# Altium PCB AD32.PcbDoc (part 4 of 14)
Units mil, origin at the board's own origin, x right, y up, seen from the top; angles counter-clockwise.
Board outline 7007.87 x 4368.85 mil, 12 copper layers (Top Layer, Int1 (GND), Int2 (AVDD), Int3 (DVDD), Int4 (GND), Int5 (ST), Int6 (SB), Int8 (AGND), Int7 (AVCC), Int9 (VCCA), Int10 (GND), Bottom Layer), stack 60.136 mil thick; 1350 components, 880 nets, 4712 pads, 2835 vias.
Unrouted connection lines stored in the file: 19.
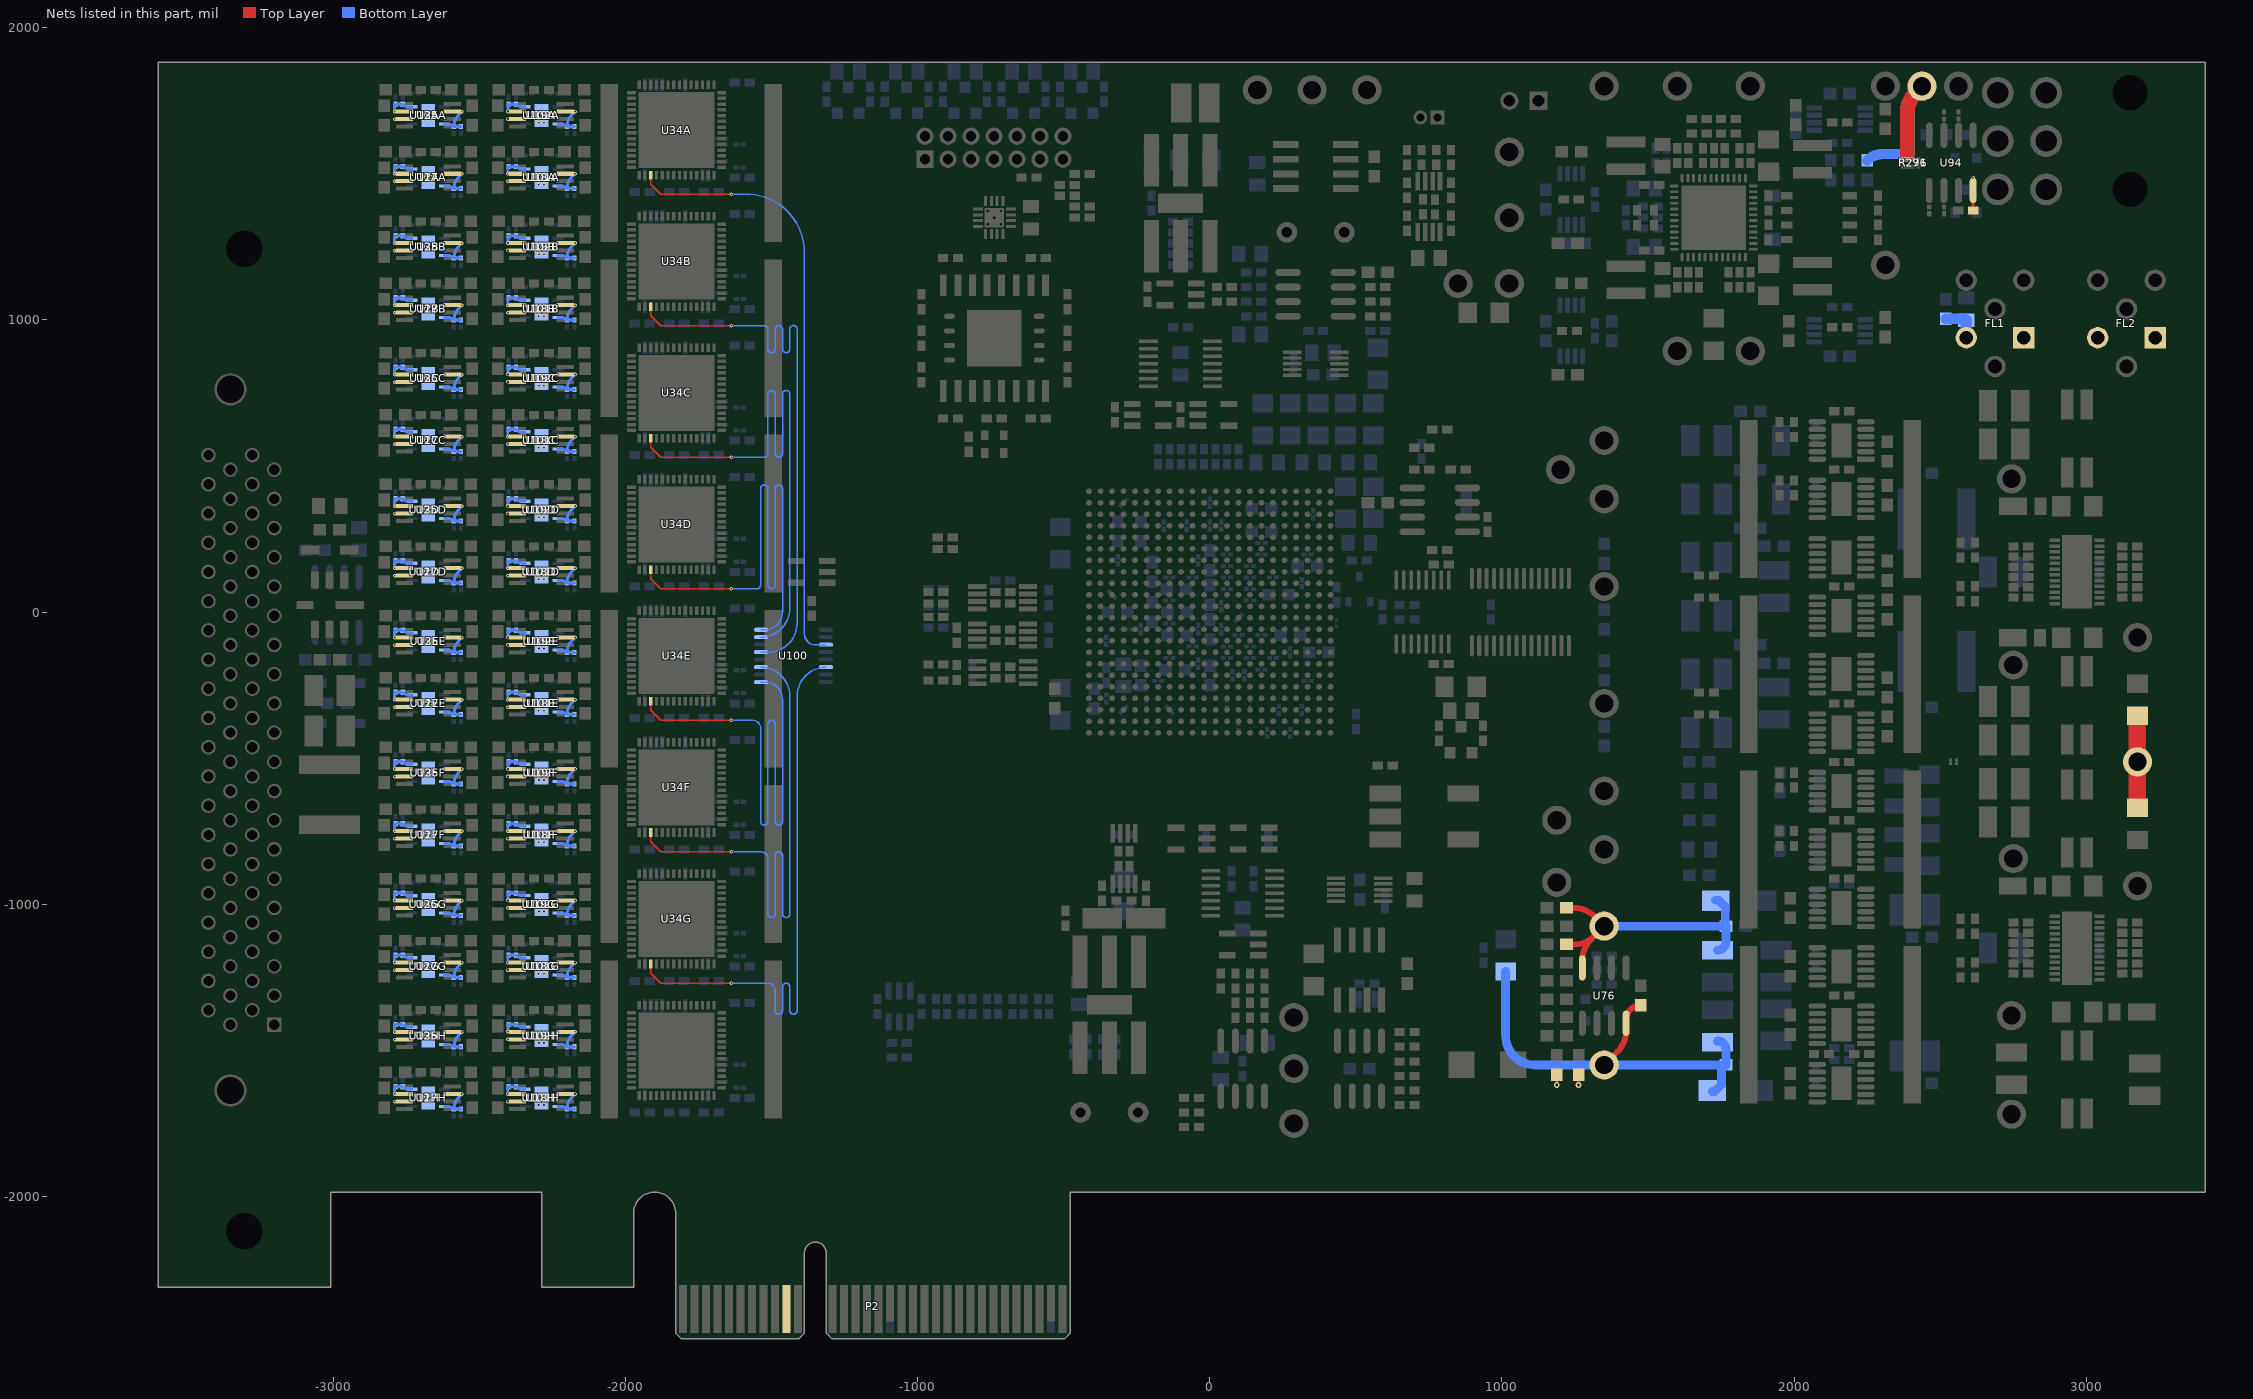
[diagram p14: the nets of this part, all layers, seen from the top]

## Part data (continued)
L3: library part CMP-11268-000187-1, "Fixed Inductors 3.3Uh Shld 5.2A 38.3mOhms AECQ2", Part Number=XFL4020-332MEC, Supplier Part Number 1=2457-XFL4020-332MEC-ND
L4: library part CMP-11268-000008-1, "INDUCTOR, 4.7uH", Part Number=XFL4020-472MEB
L5: library part MSD7342, "Shielded Coupled Inductors, MSD7342 series 4.7uH", Part Number=MSD7342-472MLC, Supplier Part Number 1=994-MSD7342-472MLC
L6 L7 L8: library part MSD7342, "Shielded Coupled Inductors, MSD7342 series 8.2uH", Part Number=MSD7342-822MLC, Supplier Part Number 1=994-MSD7342-822MLC
L9: library part ChipInductor, "Inductor", Part Number=1008CS-330XJRC, Supplier Part Number 1=2457-1008CS-330XJRC-ND
L10: library part ChipInductor, "Inductor", Part Number=1008CS-101XJRC, Supplier Part Number 1=2457-1008CS-101XJRC-ND
LOGO1: library part LIGO_logo, "NL"
MP1 MP2 MP3 MP4 MP5 MP6 MP7 MP8 MP9 MP10: library part CMP-33535-000006-1, "HEATSINK FOR TO-263", Supplier Part Number 1=DA-T263-201ECT-ND
P1: library part "PE50E-080 Connector", "3M Pak 50 plug connector", Part Number=P50E-080P1-RR1-EA, Supplier Part Number 1=3M161985-ND
P2: library part CMP-0001-00031-2, "NL"
P3: library part Xilinx_JTAG_Header, "Xilinx JTAG header, 7-Pin, Dual row", Part Number=WM18863-ND
P4: library part WM4200, "Header, 2-Pin", Supplier Part Number 1=900-0022232021-ND
Q1 Q6 Q7 Q8 Q9 Q10: "FDV301N, Digital FET, N-channel, SOT23", Part Number=FDV301NCT-ND
Q2: library part CMP-2000-07602-1, "Mosfet Array 30V 17A 2.8W Surface Mount 8-DFN (5x6)", Supplier Part Number 1=785-1499-1-ND
Q3 Q4 Q5: library part CMP-1048-00670-1, "General Purpose Transistor, PNP Silicon, 3-Pin SOT-23, Pb-Free, Tape and Reel", Supplier Part Number 1=MMBT3906LT1GOSCT-ND
R1 R197 R209 R240 R267 R537A R537B R537C R537D R537E R537F R537G R537H R538A R538B R538C R538D R538E R538F R538G R538H R585A R585B R585C R585D R585E R585F R585G R585H R593A R593B R593C R593D R593E R593F R593G R593H R601A R601B R601C R601D R601E R601F R601G R601H R609A R609B R609C R609D R609E R609F R609G R609H R649A R649B R649C R649D R649E R649F R649G R649H R657A R657B R657C R657D R657E R657F R657G R657H: library part ChipRes1, "R0603 10k", Part Number=ERA-3ARB103V, Supplier Part Number 1=P10KBDCT-ND
R2 R8 R20A R20B R20C R20D R20E R20F R20G R20H R28A R28B R28C R28D R28E R28F R28G R28H R36A R36B R36C R36D R36E R36F R36G R36H R44A R44B R44C R44D R44E R44F R44G R44H R84A R84B R84C R84D R84E R84F R84G R84H R92A R92B R92C R92D R92E R92F R92G R92H R100A R100B R100C R100D R100E R100F R100G R100H R108A R108B R108C R108D R108E R108F R108G R108H R665 R666: library part ChipRes1, "R0603 100", Part Number=ERA-3AEB101V, Supplier Part Number 1=P100DBCT-ND
R3: library part ChipRes1, "R0603 680", Part Number=RG1608P-681-B-T5, Supplier Part Number 1=RG16P680BCT-ND
R4A R4B R4C R4D R4E R4F R4G R4H R12A R12B R12C R12D R12E R12F R12G R12H R52A R52B R52C R52D R52E R52F R52G R52H R60A R60B R60C R60D R60E R60F R60G R60H R68A R68B R68C R68D R68E R68F R68G R68H R76A R76B R76C R76D R76E R76F R76G R76H R116A R116B R116C R116D R116E R116F R116G R116H R124A R124B R124C R124D R124E R124F R124G R124H: library part ChipRes1, "R0603 2.05k", Part Number=RN73C1J2K05BTD, Supplier Part Number 1=A123338CT-ND
R5 R7 R184 R193 R353 R354 R390 R391: library part ChipRes1, "R0402 49.9", Part Number=ERA-2AEB49R9X, Supplier Part Number 1=P49.9DCCT-ND
R6 R135 R136 R137 R138 R139 R142 R143 R148 R149 R150 R151 R152 R153 R162 R163 R164 R166 R167 R188 R190 R259 R328 R331 R335 R341 R368 R370 R386 R395 R397: library part ChipRes1, "R0402 NL"
R132 R141 R144 R147 R154 R159 R205 R206 R246 R256 R357 R371 R372 R374 R375: library part ChipRes1, "R0402 100", Part Number=TNPW0402100RBEED, Supplier Part Number 1=TNP100DACT-ND
R133 R134 R146 R158 R160: library part ChipRes1, "R0402 1.8k", Part Number=RR05P1.8KDCT-ND
R140 R169 R195 R373 R380 R388 R393 R398 R400: library part ChipRes1, "R0402 1.0k", Part Number=RT0402BRD071KL, Supplier Part Number 1=YAG1386CT-ND
R145 R155 R191 R293 R294 R365 R366 R367 R369 R378 R379 R381 R389 R394 R399: library part ChipRes1, "R0402 4.7k", Part Number=ERA-2AED472X, Supplier Part Number 1=P4.7KDECT-ND
R156 R157 R382: library part ChipRes1, "R0201 100", Part Number=RR0306P-101-D, Supplier Part Number 1=RR03P100DCT-ND
R161 R165: library part ChipRes1, "R0603 NL"
R168 R170 R171 R172 R173 R174 R176 R178 R179 R181 R182 R219 R225 R228 R315 R336 R339 R342 R344 R355 R361 R362: library part ChipRes1, "R0402 10k", Part Number=ERA-2AEB103X, Supplier Part Number 1=P10KDCCT-ND
R175 R180 R216 R360 R363: library part ChipRes1, "R0402 15k", Part Number=ERA-2AEB153X, Supplier Part Number 1=P15KDCCT-ND
R177 R203 R212 R304 R325 R352: library part ChipRes1, "R0603 1.0k", Part Number=RR0816P-102-D, Supplier Part Number 1=RR08P1.0KDCT-ND
R183 R220 R222 R316 R317 R337 R345 R392: library part ChipRes1, "R0402 22k", Part Number=ERA-2AED223X, Supplier Part Number 1=P22KDECT-ND
R185 R305 R307 R387: library part ChipRes1, "R0402 2.32k", Part Number=RT0402BRD072K32L, Supplier Part Number 1=YAG4228CT-ND
R186 R192: library part ChipRes1, "R0402 200k", Part Number=MCS04020D2003BE000, Supplier Part Number 1=749-MCS04020D2003BE000CT-ND
R187 R189 R277 R278 R281 R284 R376 R377: library part ChipRes1, "R0402 2k", Part Number=ERA-2AEB202X, Supplier Part Number 1=P2.0KDCCT-ND
R194 R384 R385: library part ChipRes1, "R0402 1.6k", Part Number=ERA-2AEB162X, Supplier Part Number 1=P1.6KDCCT-ND
R196 R199 R200 R201 R208 R233 R268 R308 R320 R321 R322 R323 R332 R333 R334: library part ChipRes1, "R0603 220", Part Number=ERA3AEB221V, Supplier Part Number 1=P220DBCT-ND
R198: library part ChipRes1, "R0603 1.37k", Part Number=ERA-3AEB1371V, Supplier Part Number 1=P1.37KDBCT-ND
R202 R207 R303: library part ChipRes1, "R0603 59k", Part Number=ERA-3AEB5902V, Supplier Part Number 1=P59KDBCT-ND
R204: library part ChipRes1, "R0603 3.7k", Part Number=RN73R1JTTD3701B25, Supplier Part Number 1=2019-RN73R1JTTD3701B25CT-ND
R210 R211 R236 R237 R238 R239 R243 R260 R261 R262 R263 R264 R265 R266 R298 R301 R302 R326 R327 R348 R349 R350 R351: library part ChipRes1, "R0603 10m", Part Number=CFN0603AFZ-R010ELF, Supplier Part Number 1=118-CFN0603AFZ-R010ELFCT-ND
R213 R214 R245 R255: library part ChipRes1, "R0603 5.23k", Part Number=ERA-3AEB5231V, Supplier Part Number 1=P5.23KDBCT-ND
R215 R358 R364: library part ChipRes1, "R0402 4.99k", Part Number=RR0510P-4991-D, Supplier Part Number 1=RR05P4.99KDCT-ND
R217: library part ChipRes1, "R0402 9.31k", Part Number=RT0402BRD079K31L, Supplier Part Number 1=YAG4325CT-ND
R218: library part ChipRes1, "R0402 21.5k", Part Number=RR0510P-2152-D, Supplier Part Number 1=408-RR0510P-2152-DCT-ND
R221 R223 R235 R306 R311: library part ChipRes1, "R0402 100k", Part Number=ERA-2AEB104X, Supplier Part Number 1=P100KDCCT-ND
R224: library part ChipRes1, "R0402 31.6k", Part Number=RT0402DRE0731K6L, Supplier Part Number 1=311-2272-1-ND
R226: library part ChipRes1, "R0402 12.7k", Part Number=RT0402DRE0712K7L, Supplier Part Number 1=311-2223-1-ND
R227: library part ChipRes1, "R0402 37.4k", Part Number=CR0402-FX-3742GLF, Supplier Part Number 1=YAG4250CT-ND
R229: library part ChipRes1, "R0402 7.15k", Part Number=RT0402BRD077K15L, Supplier Part Number 1=YAG1478CT-ND
R230: library part ChipRes1, "R0402 56.2k", Part Number=RT0402DRE0756K2L, Supplier Part Number 1=311-2303-1-ND
R231 R232: library part ChipRes1, "R0603 9.09k", Part Number=ERA-3AEB9091V, Supplier Part Number 1=P9.09KDBCT-ND
R234: library part ChipRes1, "R0402 130k", Part Number=RP73PF1E130KBTD, Supplier Part Number 1=A127522CT-ND
R241 R242 R312 R313: library part ChipRes1, "R0402 49.9k", Part Number=RR0510P-4992-D, Supplier Part Number 1=RR05P49.9KDCT-ND
R244: library part ChipRes1, "R0402 267k", Part Number=ERJ-2RKF2673X, Supplier Part Number 1=P267KLCT-ND
R247 R248 R252 R257: library part ChipRes1, "R0402 150", Part Number=ERA-2AEB151X, Supplier Part Number 1=P150DCCT-ND
R249 R250 R253 R254: library part ChipRes1, "R0402 300", Part Number=RR05P300DCT-ND
R251: library part ChipRes1, "R0402 249k", Part Number=RP73PF1E249KBTD, Supplier Part Number 1=A127549CT-ND
R258: library part ChipRes1, "R0402 47k", Part Number=RG1005P-473-B-T5, Supplier Part Number 1=RG10P47KBCT-ND
R269 R270 R272 R297: library part ChipRes1, "R0201 1k", Part Number=ERA-1AEB102C, Supplier Part Number 1=P1.0KBXCT-ND
R271 R296: library part RW1S0CK, "Four-Terminal Current Sense Resistor", Supplier Part Number 1=273-FC4L16R010FERCT-ND, Tolerance=0.5%
R273 R274: library part ChipRes1, "R0402 162k", Supplier Part Number 1=A127531CT-ND
R275: library part ChipRes1, "R0402 15.6k", Supplier Part Number 1=2019-RN73R1ETTP1562B25DKR-ND
R276: library part ChipRes1, "R0402 57.6k", Part Number=RT0402DRD0734K8L, Supplier Part Number 1=2019-RN73H1ETTP5762B25CT-ND
R279: library part ChipRes1, "R0402 14.7k", Part Number=RT0402BRD0714K7L, Supplier Part Number 1=YAG4174CT-ND
R280 R282 R283 R324 R330: library part ChipRes1, "R0402 0", Part Number=AC0402FR-070RL, Supplier Part Number 1=13-AC0402FR-070RLCT-ND
R285 R286 R288 R291: library part ChipRes1, "R0402 76.8k", Part Number=RT0402DRE0776K8L, Supplier Part Number 1=311-2319-1-ND
R287 R289 R290 R292: library part ChipRes1, "R0402 715k", Part Number=RC0402FR-07715KL, Supplier Part Number 1=YAG3221CT-ND
R295: library part ChipRes1, "R0603 15k", Part Number=ERA-3ARB153V, Supplier Part Number 1=P15KBDCT-ND
R299 R300: library part ChipRes1, "R0603 0", Part Number=RC0603JR-070RL, Supplier Part Number 1=311-0.0GRCT-ND
R309 R310: library part ChipRes1, "R0402 56.2k"
R314: library part ChipRes1, "R0402 12.1k", Part Number=ERA-2AEB1212X, Supplier Part Number 1=P12.1KDCCT-ND
R318 R319: library part ChipRes1, "R0402 330k", Part Number=MCS0402MD3303BE000, Supplier Part Number 1=541-MCS0402MD3303BE000CT-ND
R329: library part ChipRes1, "R0402 40.2k", Part Number=ERA-2ARC4022X, Supplier Part Number 1=P18270CT-ND
R338: library part ChipRes1, "R0402 402k", Part Number=RMCF0402FT402KCT-ND
R340: library part ChipRes1, "R0402 301k", Part Number=RMCF0402FT301KCT-ND
R343: library part ChipRes1, "R0402 1.91k", Part Number=RT0402BRD071K91L, Supplier Part Number 1=YAG4201CT-ND
R346: library part ChipRes1, "R0402 3k", Supplier Part Number 1=P3.0KDCCT-ND
R347: library part ChipRes1, "R0402 30k", Part Number=ERA-2AEB303X, Supplier Part Number 1=P30KDCCT-ND
R356 R359: library part ChipRes1, "R0402 10", Part Number=RP73PF1E10RBTD, Supplier Part Number 1=A127127CT-ND
R383: library part ChipRes1, "R0402 2.67k", Part Number=RT0402BRD072K67L, Supplier Part Number 1=YAG4234CT-ND
R396: library part ChipRes1, "R0402 15", Part Number=RP73PF1E15RBTD, Supplier Part Number 1=A127144CT-ND
R401A R401B R401C R401D R401E R401F R401G R401H R417A R417B R417C R417D R417E R417F R417G R417H R419A R419B R419C R419D R419E R419F R419G R419H R457A R457B R457C R457D R457E R457F R457G R457H R473A R473B R473C R473D R473E R473F R473G R473H: library part ChipRes1, "R0201 10k", Part Number=ERA-1AEB103C, Supplier Part Number 1=P10KBXCT-ND
R402A R402B R402C R402D R402E R402F R402G R402H: library part ChipRes1, "R0201 10K", Part Number=ERA-1AEB103C, Supplier Part Number 1=P10KBXCT-ND
R418A R418B R418C R418D R418E R418F R418G R418H: library part ChipRes1, "R0201 NL"
R553A R553B R553C R553D R553E R553F R553G R553H R554A R554B R554C R554D R554E R554F R554G R554H R569A R569B R569C R569D R569E R569F R569G R569H R577A R577B R577C R577D R577E R577F R577G R577H R617A R617B R617C R617D R617E R617F R617G R617H R618A R618B R618C R618D R618E R618F R618G R618H R633A R633B R633C R633D R633E R633F R633G R633H R634A R634B R634C R634D R634E R634F R634G R634H: library part ChipRes1, "R0201 10M", Part Number=RC0201FR-0710ML, Supplier Part Number 1=13-RC0201FR-0710MLCT-ND
S1: "Switch, SMD, 6mm", Part Number=SW262CT-ND
TP1 TP2 TP41 TP42: library part TP_SIGNAL, Part Number="Keystone / 5017", Supplier Part Number 1=36-5017CT-ND
TP3 TP5 TP6 TP7 TP27: library part TP_SIGNAL, "Testpoint, yellow", Part Number="Keystone / 5004", Supplier Part Number 1=36-5004-ND
TP4 TP8 TP9 TP10 TP11 TP12 TP17 TP18 TP19 TP20 TP21 TP22 TP23 TP26 TP28 TP29 TP30 TP31 TP35 TP36 TP37 TP38 TP39 TP40: library part TP_POSITIVE, "Testpoint, red", Part Number="Keystone / 5000", Supplier Part Number 1=36-5000-ND
TP13 TP14 TP15 TP24 TP25 TP32 TP34: library part TP_GND, "Testpoint, black", Part Number="Keystone / 5001", Supplier Part Number 1=36-5001-ND
TP16 TP33: library part TP_NEGATIVE, "Testpoint, white", Part Number="Keystone / 5002", Supplier Part Number 1=36-5002-ND
U1: library part CMP-09137-000088-1, "IC VREF SERIES 0.025% 8CLCC", Supplier Part Number 1=505-LTC6655BHLS8-4.096#PBF-ND
U2A U2B U2C U2D U2E U2F U2G U2H U3A U3B U3C U3D U3E U3F U3G U3H U18A U18B U18C U18D U18E U18F U18G U18H U19A U19B U19C U19D U19E U19F U19G U19H: "Fully Differential Amplifier", Part Number=THP210DR, Supplier Part Number 1=296-THP210DRCT-ND
U34A U34B U34C U34D U34E U34F U34G U34H: library part AD7134, "24-Bit, 4-Channel Simultaneous Sampling 1.5 MSPS Precision Alias Free ADC", Part Number=505-AD4134BCPZ-ND
U42 U53 U56 U57 U61: library part SN65LVDT2DBV, "Single LVDS Receiver with 100 Ohm termination", Part Number=296-6896-1-ND
U43: library part CMP-12948-000005-1, "IC FLASH 128M SPI 133MHZ 16SOIC", Supplier Part Number 1=MT25QU512ABB8ESF-0SIT-ND
U44: library part CMP-12948-000008-1, "IC FLASH 256M SPI 133MHZ 8WSON", Supplier Part Number 1=448-S25FL256LAGNFV010-ND
U45: "1:2 LVDS 1.8V / 2.5V Fanout Buffer for 1PPS and High-Speed Clocks", Part Number=800-2756-ND
U46 U47 U48 U52 U70: library part SN65LVDS100, "DIFF TRANSLATOR", Part Number=296-39184-1-ND
U49: library part VCXO_BomarSiTime, "Voltage controlled crystal oscillator, differential output, Bomar 14.3 x 8.7mm, or SiTime 7.0 x 5.0mm", Part Number=B1815-BA0S36LK-67.108864
U50: library part CMP-0364-00012-3, "Artix-7 FPGA, 285 User I/Os, 4 GTP, 484-Ball BGA, Speed Grade 2, Industrial Grade, Pb-Free", Part Number=XC7A200T-2FBG484C, Supplier Part Number 1=122-2080-ND
U51: library part BomarSiTime, "Voltage controlled crystal oscillator Bomar 14.3 x 8.7mm and SiTime 7.0 x 5.0mm", Part Number=B1815-BA0S36LK-47.934903
U54 U58: library part 74F74PC, "Dual D-Type Positive Edge-Triggered Flip-Flop", Supplier Part Number 1=296-1241-1-ND
U55 U60: Part Number=296-9845-1-ND
U59 U62 U65 U69 U76 U94 U98 U133: "Precision Rail-to-Rail Input and Output Operational Amplifier", Part Number=OP284FSZ-REEL7, Supplier Part Number 1=OP284FSZ-REEL7CT-ND
U63 U66: library part ADR292ER, "Low-Noise Micropower Precision Voltage Reference", Part Number=ADR425ARZ-ND, Supplier Part Number 1=505-ADR4525ARZ-ND
U64 U67: "16 bit ADC, 250kSPS, pseudo differential, serial", Part Number=AD7685BRMZRL7, Supplier Part Number 1=AD7685BRMZRL7CT-ND
U68: "Quad-Bit Dual Supply Transceiver", Part Number=SN74AVC4T245PWR, Supplier Part Number 1=296-18056-1-ND
U71: library part CMP-0798-00217-1, "1.8 to 5.5 V / 2.5 V, CMOS Low-Voltage 2.5 Ohm, 16-Channel Multiplexer, -40 to 85 degC, 28-pin SOP (RU-28), Tube", Part Number=ADG706BRUZ-REEL7, Supplier Part Number 1=ADG706BRUZ-REEL7CT-ND
U72 U73 U78 U92: library part CMP-0944-00088-2, "Low Power, Precision Instrumentation Amplifier, -40 to 125 degC, 8-pin SOP (DGK8), Green (RoHS & no Sb/Br)", Supplier Part Number 1=296-23564-1-ND
U77: library part ADP5050ACPZ-R7, "Artix 7 Power Supply", Part Number=ADP5050ACPZ-R7CT-ND, Supplier Part Number 1=505-ADP5052ACPZ-R7CT-ND
U79 U80: library part CMP-09138-000085-1, "IC REG LIN NEG ADJ 500MA 12MSOP", Supplier Part Number 1=505-LT3094IMSE#PBF-ND
U81 U82 U83 U84 U85 U86 U87 U88 U89 U90: library part CMP-09138-000053-1, "IC REG LINEAR 0V 500MA 12MSOP", Supplier Part Number 1=505-LT3045EMSE-1#PBF-ND
U95 U96: library part LT8582, "Dual 3A Boost/Inverting/SEPIC DC/DC Converter with Fault Protection", Part Number=LT8582EDKD#PBF, Supplier Part Number 1=505-LT8582EDKD#PBF-ND
U97: library part CMP-0367-00158-2, "1.25 V, 50 ppm / degC, 50 uA Series (Bandgap) Voltage Reference, -40 to 125 degC, 3-pin SOT-23 (DBZ), Green (RoHS & no Sb/Br)", Part Number=REF3012AIDBZTCT-ND
U99: library part SN74LVC1T45, "Single-Bit Dual Supply Transceiver", Part Number=SN74AVC1T45DBVT, Supplier Part Number 1=296-32277-1-ND
U100: library part CMP-0510-00563-1, "1:8 Low Jitter CMOS Clock Buffer, 1 to 200 MHz, -40 to 85 degC, 16-pin SOP", Part Number=SI53365-B-GT, Supplier Part Number 1=336-3350-ND
U101A U101B U101C U101D U101E U101F U101G U101H U102A U102B U102C U102D U102E U102F U102G U102H U117A U117B U117C U117D U117E U117F U117G U117H U125A U125B U125C U125D U125E U125F U125G U125H: library part OPA1612AID, "Dual Audio Amplifier 2 Circuit Rail-to-Rail 8-SON (3x3)", Part Number=OPA1612AIDRGT, Supplier Part Number 1=296-38372-1-ND
W1 W2: library part NetTie1_small, "NL"
W3: library part NetTie1_small
Y1: library part CMP-06255-000005-1, "MEMS OSC XO 100.0000MHZ CMOS SMD", Supplier Part Number 1=576-4966-5-ND

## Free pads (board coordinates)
  round 113.39 hole 125.2 unplated: MH1(-3304.72,-2118.5) MH2(-3304.72,1243.5)

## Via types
v1: diameter 12, hole 6, Top Layer to Bottom Layer, tented both sides, 1497 vias
v2: diameter 20, hole 10, Top Layer to Bottom Layer, tented both sides, 364 vias
v3: diameter 19, hole 10, Top Layer to Bottom Layer, tented both sides, 347 vias
v4: diameter 14, hole 7, Top Layer to Bottom Layer, tented both sides, 228 vias
v5: diameter 19.68, hole 7.87, Top Layer to Bottom Layer, 225 vias
v6: diameter 19.02, hole 10, Top Layer to Bottom Layer, tented both sides, 85 vias
v7: diameter 20, hole 10, Top Layer to Bottom Layer, 32 vias
v8: diameter 40, hole 20, Top Layer to Bottom Layer, tented both sides, 14 vias
v9: diameter 30, hole 15, Top Layer to Bottom Layer, tented both sides, 12 vias
v10: diameter 25, hole 13, Top Layer to Bottom Layer, 8 vias
v11: diameter 40, hole 20, Top Layer to Bottom Layer, 6 vias
v12: diameter 50, hole 20, Top Layer to Bottom Layer, 6 vias
v13: diameter 66, hole 47, Top Layer to Bottom Layer, tented both sides, 3 vias
v14: diameter 63, hole 45, Top Layer to Bottom Layer, 2 vias
v15: diameter 50, hole 25, Top Layer to Bottom Layer, 2 vias
v16: diameter 12, hole 6, Top Layer to Bottom Layer, 2 vias
v17: diameter 60, hole 40, Top Layer to Bottom Layer, tented both sides, 1 vias
v18: diameter 60, hole 40, Top Layer to Bottom Layer, 1 vias

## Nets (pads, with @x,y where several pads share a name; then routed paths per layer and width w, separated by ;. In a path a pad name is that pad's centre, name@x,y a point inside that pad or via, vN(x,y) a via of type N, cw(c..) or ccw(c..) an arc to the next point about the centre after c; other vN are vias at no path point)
3.3Vaux: P2.B10
12V: C110.1 FL1.1 FL2.1 R271.1 R296.4 R303.1 TP31.1 U94.8 | length 753
  Top Layer w10: v1(2612.5,1486.32) U94.8@2612.5,1443.01 2612.5,1375 C110.1@2613.09,1375
  Top Layer w50: 2387.5,1567.5 2387.5,1708.58 cw(c2487.5,1708.58) 2416.79,1779.29 TP31.1@2437.5,1800
  Bottom Layer w35: R303.1@2250,1545.96 cw(c2301.99,1493.97) 2301.99,1567.5 2387.5,1567.5
  Bottom Layer w50: 2387.5,1567.5 2387.5,1708.58 cw(c2487.5,1708.58) 2416.79,1779.29 TP31.1@2437.5,1800
12VA: FL2.2 FR5.1 FR6.1 TP39.1 | length 314.8
  Top Layer w60: FR5.1@3175,-669.88 TP39.1@3175,-512.5 FR6.1@3175,-355.12
12VF: C111.1 FL1.2 R298.2 | length 131.7
  Bottom Layer w35: R298.2@2518.75,1004.04 2577.19,1004.04 cw(c2577.19,987.23) C111.1@2589.07,999.11
  Bottom Layer w40: FL1.2@2589.07,939.07 C111.1@2589.07,999.11
+15V: C63.2 C129.2 C384A.2 C384B.2 C384C.2 C384D.2 C384E.2 C384F.2 C384G.2 C384H.2 C385A.2 C385B.2 C385C.2 C385D.2 C385E.2 C385F.2 C385G.2 C385H.2 C432A.1 C432B.1 C432C.1 C432D.1 C432E.1 C432F.1 C432G.1 C432H.1 C440A.1 C440B.1 C440C.1 C440D.1 C440E.1 C440F.1 C440G.1 C440H.1 C448A.2 C448B.2 C448C.2 C448D.2 C448E.2 C448F.2 C448G.2 C448H.2 C449A.2 C449B.2 C449C.2 C449D.2 C449E.2 C449F.2 C449G.2 C449H.2 C480A.1 C480B.1 C480C.1 C480D.1 C480E.1 C480F.1 C480G.1 C480H.1 C504A.1 C504B.1 C504C.1 C504D.1 C504E.1 C504F.1 C504G.1 C504H.1 D9.2 R202.1 R327.1 TP17.1 U2A.3 U2A.7 U2B.3 U2B.7 U2C.3 U2C.7 U2D.3 U2D.7 U2E.3 U2E.7 U2F.3 U2F.7 U2G.3 U2G.7 U2H.3 U2H.7 U3A.3 U3A.7 U3B.3 U3B.7 U3C.3 U3C.7 U3D.3 U3D.7 U3E.3 U3E.7 U3F.3 U3F.7 U3G.3 U3G.7 U3H.3 U3H.7 U18A.3 U18A.7 U18B.3 U18B.7 U18C.3 U18C.7 U18D.3 U18D.7 U18E.3 U18E.7 U18F.3 U18F.7 U18G.3 U18G.7 U18H.3 U18H.7 U19A.3 U19A.7 U19B.3 U19B.7 U19C.3 U19C.7 U19D.3 U19D.7 U19E.3 U19E.7 U19F.3 U19F.7 U19G.3 U19G.7 U19H.3 U19H.7 U76.8 U101A.8 U101B.8 U101C.8 U101D.8 U101E.8 U101F.8 U101G.8 U101H.8 U102A.8 U102B.8 U102C.8 U102D.8 U102E.8 U102F.8 U102G.8 U102H.8 U117A.8 U117B.8 U117C.8 U117D.8 U117E.8 U117F.8 U117G.8 U117H.8 U125A.8 U125B.8 U125C.8 U125D.8 U125E.8 U125F.8 U125G.8 U125H.8 | length 6986.1
  Top Layer w10: v1(-2790,-1675.3) U2H.7@-2756.69,-1675.29 ; v1(-2790,-1462.92) U3H.7@-2756.69,-1462.92 ; v1(-2790,-1225.3) U2G.7@-2756.69,-1225.29 ; v1(-2790,-1012.92) U3G.7@-2756.69,-1012.92 ; v1(-2790,-775.3) U2F.7@-2756.69,-775.29 ; v1(-2790,-562.92) U3F.7@-2756.69,-562.92 ; v1(-2790,-325.3) U2E.7@-2756.69,-325.29 ; v1(-2790,-112.92) U3E.7@-2756.69,-112.92 ; v1(-2790,124.7) U2D.7@-2756.69,124.71 ; v1(-2790,337.08) U3D.7@-2756.69,337.08 ; v1(-2790,574.7) U2C.7@-2756.69,574.71 ; v1(-2790,787.08) U3C.7@-2756.69,787.08 ; v1(-2790,1024.7) U2B.7@-2756.69,1024.71 ; v1(-2790,1237.08) U3B.7@-2756.69,1237.08 ; v1(-2790,1474.7) U2A.7@-2756.69,1474.71 ; v1(-2790,1687.08) U3A.7@-2756.69,1687.08 ; U2H.3@-2593.31,-1649.7 -2592.92,-1650.09 -2560.38,-1650.09 v1(-2560,-1649.71) ; U3H.3@-2593.31,-1437.33 v1(-2560,-1437.33) ; U2G.3@-2593.31,-1199.7 -2592.92,-1200.09 -2560.38,-1200.09 v1(-2560,-1199.71) ; U3G.3@-2593.31,-987.33 v1(-2560,-987.33) ; U2F.3@-2593.31,-749.7 -2592.92,-750.09 -2560.38,-750.09 v1(-2560,-749.71) ; U3F.3@-2593.31,-537.33 v1(-2560,-537.33) ; U2E.3@-2593.31,-299.7 -2592.92,-300.09 -2560.38,-300.09 v1(-2560,-299.71) ; U3E.3@-2593.31,-87.33 v1(-2560,-87.33) ; U2D.3@-2593.31,150.3 -2592.92,149.91 -2560.38,149.91 v1(-2560,150.29) ; U3D.3@-2593.31,362.67 v1(-2560,362.67) ; U2C.3@-2593.31,600.3 -2592.92,599.91 -2560.38,599.91 v1(-2560,600.29) ; U3C.3@-2593.31,812.67 v1(-2560,812.67) ; U2B.3@-2593.31,1050.3 -2592.92,1049.91 -2560.38,1049.91 v1(-2560,1050.29) ; U3B.3@-2593.31,1262.67 v1(-2560,1262.67) ; U2A.3@-2593.31,1500.3 -2592.92,1499.91 -2560.38,1499.91 v1(-2560,1500.29) ; U3A.3@-2593.31,1712.67 v1(-2560,1712.67) ; v1(-2402.5,-1675.29) U18H.7@-2369.19,-1675.29 ; v1(-2402.5,-1462.3) -2402.25,-1462.54 -2369.44,-1462.54 U19H.7@-2369.19,-1462.79 ; v1(-2402.5,-1225.29) U18G.7@-2369.19,-1225.29 ; v1(-2402.5,-1012.3) -2402.25,-1012.54 -2369.44,-1012.54 U19G.7@-2369.19,-1012.79 ; v1(-2402.5,-775.29) U18F.7@-2369.19,-775.29 ; v1(-2402.5,-562.3) -2402.25,-562.54 -2369.44,-562.54 U19F.7@-2369.19,-562.79 ; v1(-2402.5,-325.29) U18E.7@-2369.19,-325.29 ; v1(-2402.5,-112.3) -2402.25,-112.55 -2369.44,-112.55 U19E.7@-2369.19,-112.79 ; v1(-2402.5,124.71) U18D.7@-2369.19,124.71 ; v1(-2402.5,337.7) -2402.25,337.45 -2369.44,337.45 U19D.7@-2369.19,337.21 ; v1(-2402.5,574.71) U18C.7@-2369.19,574.71 ; v1(-2402.5,787.7) -2402.25,787.45 -2369.44,787.45 U19C.7@-2369.19,787.21 ; v1(-2402.5,1024.71) U18B.7@-2369.19,1024.71 ; v1(-2402.5,1237.7) -2402.25,1237.45 -2369.44,1237.45 U19B.7@-2369.19,1237.21 ; v1(-2402.5,1474.71) U18A.7@-2369.19,1474.71 ; v1(-2402.5,1687.7) -2402.25,1687.45 -2369.44,1687.45 U19A.7@-2369.19,1687.21 ; U18H.3@-2205.81,-1649.7 v1(-2172.5,-1649.7) ; U19H.3@-2205.81,-1437.2 -2205.56,-1436.95 -2172.36,-1436.95 v1(-2172.11,-1436.71) ; U18G.3@-2205.81,-1199.7 v1(-2172.5,-1199.7) ; U19G.3@-2205.81,-987.2 -2205.56,-986.95 -2172.36,-986.95 v1(-2172.11,-986.71) ; U18F.3@-2205.81,-749.7 v1(-2172.5,-749.7) ; U19F.3@-2205.81,-537.2 -2205.56,-536.95 -2172.36,-536.95 v1(-2172.11,-536.71) ; U18E.3@-2205.81,-299.7 v1(-2172.5,-299.7) ; U19E.3@-2205.81,-87.2 -2205.56,-86.96 -2172.36,-86.96 v1(-2172.11,-86.71) ; U18D.3@-2205.81,150.3 v1(-2172.5,150.3) ; U19D.3@-2205.81,362.8 -2205.56,363.04 -2172.36,363.04 v1(-2172.11,363.29) ; U18C.3@-2205.81,600.3 v1(-2172.5,600.3) ; U19C.3@-2205.81,812.8 -2205.56,813.04 -2172.36,813.04 v1(-2172.11,813.29) ; U18B.3@-2205.81,1050.3 v1(-2172.5,1050.3) ; U19B.3@-2205.81,1262.8 -2205.56,1263.04 -2172.36,1263.04 v1(-2172.11,1263.29) ; U18A.3@-2205.81,1500.3 v1(-2172.5,1500.3) ; U19A.3@-2205.81,1712.8 -2205.56,1713.04 -2172.36,1713.04 v1(-2172.11,1713.29)
  Top Layer w20: R202.1@1220.96,-1137.5 1246.08,-1137.5 ccw(c1246.08,-1037.5) TP17.1@1316.79,-1108.21 ; C63.2@1220.96,-1012.5 1246.08,-1012.5 cw(c1246.08,-1112.5) 1316.79,-1041.79 TP17.1@1350,-1075 TP17.1@1316.79,-1108.21 ; U76.8@1275,-1218.01 1275,-1191.42 cw(c1375,-1191.42) 1304.29,-1120.71 TP17.1@1316.79,-1108.21
  Bottom Layer w10: U117H.8@-2618.89,-1692.03 -2608.11,-1692.03 cw(c-2608.11,-1721.17) C480H.1@-2587.5,-1700.56 ; U125H.8@-2618.89,-1479.65 -2607.8,-1479.65 cw(c-2607.8,-1508.37) C449H.2@-2587.5,-1488.06 ; U117G.8@-2618.89,-1242.03 -2608.11,-1242.03 cw(c-2608.11,-1271.17) C480G.1@-2587.5,-1250.56 ; U125G.8@-2618.89,-1029.65 -2607.8,-1029.65 cw(c-2607.8,-1058.37) C449G.2@-2587.5,-1038.06 ; U117F.8@-2618.89,-792.03 -2608.11,-792.03 cw(c-2608.11,-821.17) C480F.1@-2587.5,-800.56 ; U125F.8@-2618.89,-579.65 -2607.8,-579.65 cw(c-2607.8,-608.37) C449F.2@-2587.5,-588.06 ; U117E.8@-2618.89,-342.03 -2608.11,-342.03 cw(c-2608.11,-371.17) C480E.1@-2587.5,-350.56 ; U125E.8@-2618.89,-129.65 -2607.8,-129.65 cw(c-2607.8,-158.37) C449E.2@-2587.5,-138.06 ; U117D.8@-2618.89,107.97 -2608.11,107.97 cw(c-2608.11,78.83) C480D.1@-2587.5,99.44 ; U125D.8@-2618.89,320.35 -2607.8,320.35 cw(c-2607.8,291.63) C449D.2@-2587.5,311.94 ; U117C.8@-2618.89,557.97 -2608.11,557.97 cw(c-2608.11,528.83) C480C.1@-2587.5,549.44 ; U125C.8@-2618.89,770.35 -2607.8,770.35 cw(c-2607.8,741.63) C449C.2@-2587.5,761.94 ; U117B.8@-2618.89,1007.97 -2608.11,1007.97 cw(c-2608.11,978.83) C480B.1@-2587.5,999.44 ; U125B.8@-2618.89,1220.35 -2607.8,1220.35 cw(c-2607.8,1191.63) C449B.2@-2587.5,1211.94 ; U117A.8@-2618.89,1457.97 -2608.11,1457.97 cw(c-2608.11,1428.83) C480A.1@-2587.5,1449.44 ; U125A.8@-2618.89,1670.35 -2607.8,1670.35 cw(c-2607.8,1641.63) C449A.2@-2587.5,1661.94 ; C448H.2@-2562.5,-1700.56 C480H.1@-2587.5,-1700.56 ; C504H.1@-2562.5,-1488.06 C449H.2@-2587.5,-1488.06 ; C448G.2@-2562.5,-1250.56 C480G.1@-2587.5,-1250.56 ; C504G.1@-2562.5,-1038.06 C449G.2@-2587.5,-1038.06 ; C448F.2@-2562.5,-800.56 C480F.1@-2587.5,-800.56 ; C504F.1@-2562.5,-588.06 C449F.2@-2587.5,-588.06 ; C448E.2@-2562.5,-350.56 C480E.1@-2587.5,-350.56 ; C504E.1@-2562.5,-138.06 C449E.2@-2587.5,-138.06 ; C448D.2@-2562.5,99.44 C480D.1@-2587.5,99.44 ; C504D.1@-2562.5,311.94 C449D.2@-2587.5,311.94 ; C448C.2@-2562.5,549.44 C480C.1@-2587.5,549.44 ; C504C.1@-2562.5,761.94 C449C.2@-2587.5,761.94 ; C448B.2@-2562.5,999.44 C480B.1@-2587.5,999.44 ; C504B.1@-2562.5,1211.94 C449B.2@-2587.5,1211.94 ; C448A.2@-2562.5,1449.44 C480A.1@-2587.5,1449.44 ; C504A.1@-2562.5,1661.94 C449A.2@-2587.5,1661.94 ; v1(-2560,-1649.71) -2570.98,-1660.69 ccw(c-2531.11,-1700.56) C480H.1@-2587.5,-1700.56 ; v1(-2560,-1437.33) -2571.07,-1448.4 ccw(c-2531.41,-1488.06) C449H.2@-2587.5,-1488.06 ; v1(-2560,-1199.71) -2570.98,-1210.69 ccw(c-2531.11,-1250.56) C480G.1@-2587.5,-1250.56 ; v1(-2560,-987.33) -2571.07,-998.4 ccw(c-2531.41,-1038.06) C449G.2@-2587.5,-1038.06 ; v1(-2560,-749.71) -2570.98,-760.69 ccw(c-2531.11,-800.56) C480F.1@-2587.5,-800.56 ; v1(-2560,-537.33) -2571.07,-548.4 ccw(c-2531.41,-588.06) C449F.2@-2587.5,-588.06 ; v1(-2560,-299.71) -2570.98,-310.69 ccw(c-2531.11,-350.56) C480E.1@-2587.5,-350.56 ; v1(-2560,-87.33) -2571.07,-98.4 ccw(c-2531.41,-138.06) C449E.2@-2587.5,-138.06 ; v1(-2560,150.29) -2570.98,139.31 ccw(c-2531.11,99.44) C480D.1@-2587.5,99.44 ; v1(-2560,362.67) -2571.07,351.6 ccw(c-2531.41,311.94) C449D.2@-2587.5,311.94 ; v1(-2560,600.29) -2570.98,589.31 ccw(c-2531.11,549.44) C480C.1@-2587.5,549.44 ; v1(-2560,812.67) -2571.07,801.6 ccw(c-2531.41,761.94) C449C.2@-2587.5,761.94 ; v1(-2560,1050.29) -2570.98,1039.31 ccw(c-2531.11,999.44) C480B.1@-2587.5,999.44 ; v1(-2560,1262.67) -2571.07,1251.6 ccw(c-2531.41,1211.94) C449B.2@-2587.5,1211.94 ; v1(-2560,1500.29) -2570.98,1489.31 ccw(c-2531.11,1449.44) C480A.1@-2587.5,1449.44 ; v1(-2560,1712.67) -2571.07,1701.6 ccw(c-2531.41,1661.94) C449A.2@-2587.5,1661.94 ; U101H.8@-2231.39,-1692.03 -2220.61,-1692.03 cw(c-2220.61,-1721.17) C440H.1@-2200,-1700.56 ; U102H.8@-2231.39,-1479.53 -2220.61,-1479.53 cw(c-2220.61,-1508.67) C385H.2@-2200,-1488.06 ; U101G.8@-2231.39,-1242.03 -2220.61,-1242.03 cw(c-2220.61,-1271.17) C440G.1@-2200,-1250.56 ; U102G.8@-2231.39,-1029.53 -2220.61,-1029.53 cw(c-2220.61,-1058.67) C385G.2@-2200,-1038.06 ; U101F.8@-2231.39,-792.03 -2220.61,-792.03 cw(c-2220.61,-821.17) C440F.1@-2200,-800.56 ; U102F.8@-2231.39,-579.53 -2220.61,-579.53 cw(c-2220.61,-608.67) C385F.2@-2200,-588.06 ; U101E.8@-2231.39,-342.03 -2220.61,-342.03 cw(c-2220.61,-371.17) C440E.1@-2200,-350.56 ; U102E.8@-2231.39,-129.53 -2220.61,-129.53 cw(c-2220.61,-158.67) C385E.2@-2200,-138.06 ; U101D.8@-2231.39,107.97 -2220.61,107.97 cw(c-2220.61,78.83) C440D.1@-2200,99.44 ; U102D.8@-2231.39,320.47 -2220.61,320.47 cw(c-2220.61,291.33) C385D.2@-2200,311.94 ; U101C.8@-2231.39,557.97 -2220.61,557.97 cw(c-2220.61,528.83) C440C.1@-2200,549.44 ; U102C.8@-2231.39,770.47 -2220.61,770.47 cw(c-2220.61,741.33) C385C.2@-2200,761.94 ; U101B.8@-2231.39,1007.97 -2220.61,1007.97 cw(c-2220.61,978.83) C440B.1@-2200,999.44 ; U102B.8@-2231.39,1220.47 -2220.61,1220.47 cw(c-2220.61,1191.33) C385B.2@-2200,1211.94 ; U101A.8@-2231.39,1457.97 -2220.61,1457.97 cw(c-2220.61,1428.83) C440A.1@-2200,1449.44 ; U102A.8@-2231.39,1670.47 -2220.61,1670.47 cw(c-2220.61,1641.33) C385A.2@-2200,1661.94 ; C384H.2@-2175,-1700.56 C440H.1@-2200,-1700.56 ; C432H.1@-2175,-1488.06 C385H.2@-2200,-1488.06 ; C384G.2@-2175,-1250.56 C440G.1@-2200,-1250.56 ; C432G.1@-2175,-1038.06 C385G.2@-2200,-1038.06 ; C384F.2@-2175,-800.56 C440F.1@-2200,-800.56 ; C432F.1@-2175,-588.06 C385F.2@-2200,-588.06 ; C384E.2@-2175,-350.56 C440E.1@-2200,-350.56 ; C432E.1@-2175,-138.06 C385E.2@-2200,-138.06 ; C384D.2@-2175,99.44 C440D.1@-2200,99.44 ; C432D.1@-2175,311.94 C385D.2@-2200,311.94 ; C384C.2@-2175,549.44 C440C.1@-2200,549.44 ; C432C.1@-2175,761.94 C385C.2@-2200,761.94 ; C384B.2@-2175,999.44 C440B.1@-2200,999.44 ; C432B.1@-2175,1211.94 C385B.2@-2200,1211.94 ; C384A.2@-2175,1449.44 C440A.1@-2200,1449.44 ; C432A.1@-2175,1661.94 C385A.2@-2200,1661.94 ; v1(-2172.5,-1649.7) -2183.48,-1660.69 ccw(c-2143.61,-1700.56) C440H.1@-2200,-1700.56 ; v1(-2172.5,-1199.7) -2183.48,-1210.69 ccw(c-2143.61,-1250.56) C440G.1@-2200,-1250.56 ; v1(-2172.5,-749.7) -2183.48,-760.69 ccw(c-2143.61,-800.56) C440F.1@-2200,-800.56 ; v1(-2172.5,-299.7) -2183.48,-310.69 ccw(c-2143.61,-350.56) C440E.1@-2200,-350.56 ; v1(-2172.5,150.3) -2183.48,139.31 ccw(c-2143.61,99.44) C440D.1@-2200,99.44 ; v1(-2172.5,600.3) -2183.48,589.31 ccw(c-2143.61,549.44) C440C.1@-2200,549.44 ; v1(-2172.5,1050.3) -2183.48,1039.31 ccw(c-2143.61,999.44) C440B.1@-2200,999.44 ; v1(-2172.5,1500.3) -2183.48,1489.31 ccw(c-2143.61,1449.44) C440A.1@-2200,1449.44 ; v1(-2172.11,-1436.71) -2183.41,-1448.01 ccw(c-2143.35,-1488.06) C385H.2@-2200,-1488.06 ; v1(-2172.11,-986.71) -2183.41,-998.01 ccw(c-2143.35,-1038.06) C385G.2@-2200,-1038.06 ; v1(-2172.11,-536.71) -2183.41,-548.01 ccw(c-2143.35,-588.06) C385F.2@-2200,-588.06 ; v1(-2172.11,-86.71) -2183.41,-98.01 ccw(c-2143.35,-138.06) C385E.2@-2200,-138.06 ; v1(-2172.11,363.29) -2183.41,351.99 ccw(c-2143.35,311.94) C385D.2@-2200,311.94 ; v1(-2172.11,813.29) -2183.41,801.99 ccw(c-2143.35,761.94) C385C.2@-2200,761.94 ; v1(-2172.11,1263.29) -2183.41,1251.99 ccw(c-2143.35,1211.94) C385B.2@-2200,1211.94 ; v1(-2172.11,1713.29) -2183.41,1701.99 ccw(c-2143.35,1661.94) C385A.2@-2200,1661.94
  Bottom Layer w30: TP17.1@1350,-1075 R327.1@1766.54,-1075 ; D9.2@1731.25,-986.25 1742.35,-986.25 1764.04,-1007.93 1764.04,-1072.5 R327.1@1766.54,-1075 ; C129.2@1737.5,-1157.38 ccw(c1737.5,-1128.35) 1766.54,-1128.35 R327.1@1766.54,-1075
-15V: C67.2 C128.1 C400A.1 C400B.1 C400C.1 C400D.1 C400E.1 C400F.1 C400G.1 C400H.1 C401A.1 C401B.1 C401C.1 C401D.1 C401E.1 C401F.1 C401G.1 C401H.1 C416A.2 C416B.2 C416C.2 C416D.2 C416E.2 C416F.2 C416G.2 C416H.2 C424A.2 C424B.2 C424C.2 C424D.2 C424E.2 C424F.2 C424G.2 C424H.2 C464A.1 C464B.1 C464C.1 C464D.1 C464E.1 C464F.1 C464G.1 C464H.1 C465A.1 C465B.1 C465C.1 C465D.1 C465E.1 C465F.1 C465G.1 C465H.1 C488A.2 C488B.2 C488C.2 C488D.2 C488E.2 C488F.2 C488G.2 C488H.2 C496A.2 C496B.2 C496C.2 C496D.2 C496E.2 C496F.2 C496G.2 C496H.2 D10.1 FR7.1 R207.2 R212.1 R326.1 TP16.1 U2A.6 U2B.6 U2C.6 U2D.6 U2E.6 U2F.6 U2G.6 U2H.6 U3A.6 U3B.6 U3C.6 U3D.6 U3E.6 U3F.6 U3G.6 U3H.6 U18A.6 U18B.6 U18C.6 U18D.6 U18E.6 U18F.6 U18G.6 U18H.6 U19A.6 U19B.6 U19C.6 U19D.6 U19E.6 U19F.6 U19G.6 U19H.6 U76.4 U101A.4 U101A.9 U101B.4 U101B.9 U101C.4 U101C.9 U101D.4 U101D.9 U101E.4 U101E.9 U101F.4 U101F.9 U101G.4 U101G.9 U101H.4 U101H.9 U102A.4 U102A.9 U102B.4 U102B.9 U102C.4 U102C.9 U102D.4 U102D.9 U102E.4 U102E.9 U102F.4 U102F.9 U102G.4 U102G.9 U102H.4 U102H.9 U117A.4 U117A.9 U117B.4 U117B.9 U117C.4 U117C.9 U117D.4 U117D.9 U117E.4 U117E.9 U117F.4 U117F.9 U117G.4 U117G.9 U117H.4 U117H.9 U125A.4 U125A.9 U125B.4 U125B.9 U125C.4 U125C.9 U125D.4 U125D.9 U125E.4 U125E.9 U125F.4 U125F.9 U125G.4 U125G.9 U125H.4 U125H.9 | length 5363.6
  Top Layer w10: v1(-2790,-1649.71) U2H.6@-2756.69,-1649.7 ; v1@-2789.99,-1437.35 U3H.6@-2756.69,-1437.33 ; v1(-2790,-1199.71) U2G.6@-2756.69,-1199.7 ; v1@-2789.99,-987.35 U3G.6@-2756.69,-987.33 ; v1(-2790,-749.71) U2F.6@-2756.69,-749.7 ; v1@-2789.99,-537.35 U3F.6@-2756.69,-537.33 ; v1(-2790,-299.71) U2E.6@-2756.69,-299.7 ; v1@-2789.99,-87.35 U3E.6@-2756.69,-87.33 ; v1(-2790,150.29) U2D.6@-2756.69,150.3 ; v1@-2789.99,362.65 U3D.6@-2756.69,362.67 ; v1(-2790,600.29) U2C.6@-2756.69,600.3 ; v1@-2789.99,812.65 U3C.6@-2756.69,812.67 ; v1(-2790,1050.29) U2B.6@-2756.69,1050.3 ; v1@-2789.99,1262.65 U3B.6@-2756.69,1262.67 ; v1(-2790,1500.29) U2A.6@-2756.69,1500.3 ; v1@-2789.99,1712.65 U3A.6@-2756.69,1712.67 ; v1(-2402.89,-1649.7) U18H.6@-2369.19,-1649.7 ; v1(-2402.89,-1199.7) U18G.6@-2369.19,-1199.7 ; v1(-2402.89,-749.7) U18F.6@-2369.19,-749.7 ; v1(-2402.89,-299.7) U18E.6@-2369.19,-299.7 ; v1(-2402.89,150.3) U18D.6@-2369.19,150.3 ; v1(-2402.89,600.3) U18C.6@-2369.19,600.3 ; v1(-2402.89,1050.3) U18B.6@-2369.19,1050.3 ; v1(-2402.89,1500.3) U18A.6@-2369.19,1500.3 ; v1(-2402.5,-1436.71) -2402.25,-1436.95 -2369.44,-1436.95 U19H.6@-2369.19,-1437.2 ; v1(-2402.5,-986.71) -2402.25,-986.95 -2369.44,-986.95 U19G.6@-2369.19,-987.2 ; v1(-2402.5,-536.71) -2402.25,-536.95 -2369.44,-536.95 U19F.6@-2369.19,-537.2 ; v1(-2402.5,-86.71) -2402.25,-86.96 -2369.44,-86.96 U19E.6@-2369.19,-87.2 ; v1(-2402.5,363.29) -2402.25,363.04 -2369.44,363.04 U19D.6@-2369.19,362.8 ; v1(-2402.5,813.29) -2402.25,813.04 -2369.44,813.04 U19C.6@-2369.19,812.8 ; v1(-2402.5,1263.29) -2402.25,1263.04 -2369.44,1263.04 U19B.6@-2369.19,1262.8 ; v1(-2402.5,1713.29) -2402.25,1713.04 -2369.44,1713.04 U19A.6@-2369.19,1712.8 ; v2(1187.5,-1618.96) R207.2@1187.5,-1583.46 ; v2(1262.5,-1618.96) R212.1@1262.5,-1583.46
  Top Layer w20: TP16.1@1350,-1550 1395.71,-1504.29 ccw(c1325,-1433.58) 1425,-1433.58 U76.4@1425,-1406.99 1425,-1395.96 cw(c1475,-1395.96) C67.2@1475,-1345.96
  Top Layer w30: TP16.1@1350,-1562.61 TP16.1@1350,-1550
  Bottom Layer w10: v1(-2790,-1649.71) -2790,-1630.47 cw(c-2781.46,-1630.47) C464H.1@-2787.5,-1624.44 C496H.2@-2762.5,-1624.44 ccw(c-2741.89,-1603.83) -2741.89,-1632.97 U117H.4@-2731.1,-1632.97 ; v1(-2790,-1437.36) -2790,-1417.97 cw(c-2781.46,-1417.97) C465H.1@-2787.5,-1411.94 C488H.2@-2762.5,-1411.94 ccw(c-2741.59,-1391.03) -2741.59,-1420.6 U125H.4@-2731.1,-1420.6 ; v1(-2790,-1199.71) -2790,-1180.47 cw(c-2781.46,-1180.47) C464G.1@-2787.5,-1174.44 C496G.2@-2762.5,-1174.44 ccw(c-2741.89,-1153.83) -2741.89,-1182.97 U117G.4@-2731.1,-1182.97 ; v1(-2790,-987.36) -2790,-967.97 cw(c-2781.46,-967.97) C465G.1@-2787.5,-961.94 C488G.2@-2762.5,-961.94 ccw(c-2741.59,-941.03) -2741.59,-970.6 U125G.4@-2731.1,-970.6 ; v1(-2790,-749.71) -2790,-730.47 cw(c-2781.46,-730.47) C464F.1@-2787.5,-724.44 C496F.2@-2762.5,-724.44 ccw(c-2741.89,-703.83) -2741.89,-732.97 U117F.4@-2731.1,-732.97 ; v1(-2790,-537.36) -2790,-517.97 cw(c-2781.46,-517.97) C465F.1@-2787.5,-511.94 C488F.2@-2762.5,-511.94 ccw(c-2741.59,-491.03) -2741.59,-520.6 U125F.4@-2731.1,-520.6 ; v1(-2790,-299.71) -2790,-280.47 cw(c-2781.46,-280.47) C464E.1@-2787.5,-274.44 C496E.2@-2762.5,-274.44 ccw(c-2741.89,-253.83) -2741.89,-282.97 U117E.4@-2731.1,-282.97 ; v1(-2790,-87.36) -2790,-67.97 cw(c-2781.46,-67.97) C465E.1@-2787.5,-61.94 C488E.2@-2762.5,-61.94 ccw(c-2741.59,-41.03) -2741.59,-70.6 U125E.4@-2731.1,-70.6 ; v1(-2790,150.29) -2790,169.53 cw(c-2781.46,169.53) C464D.1@-2787.5,175.56 C496D.2@-2762.5,175.56 ccw(c-2741.89,196.17) -2741.89,167.03 U117D.4@-2731.1,167.03 ; v1(-2790,362.64) -2790,382.03 cw(c-2781.46,382.03) C465D.1@-2787.5,388.06 C488D.2@-2762.5,388.06 ccw(c-2741.59,408.97) -2741.59,379.4 U125D.4@-2731.1,379.4 ; v1(-2790,600.29) -2790,619.53 cw(c-2781.46,619.53) C464C.1@-2787.5,625.56 C496C.2@-2762.5,625.56 ccw(c-2741.89,646.17) -2741.89,617.03 U117C.4@-2731.1,617.03 ; v1(-2790,812.64) -2790,832.03 cw(c-2781.46,832.03) C465C.1@-2787.5,838.06 C488C.2@-2762.5,838.06 ccw(c-2741.59,858.97) -2741.59,829.4 U125C.4@-2731.1,829.4 ; v1(-2790,1050.29) -2790,1069.53 cw(c-2781.46,1069.53) C464B.1@-2787.5,1075.56 C496B.2@-2762.5,1075.56 ccw(c-2741.89,1096.17) -2741.89,1067.03 U117B.4@-2731.1,1067.03 ; v1(-2790,1262.64) -2790,1282.03 cw(c-2781.46,1282.03) C465B.1@-2787.5,1288.06 C488B.2@-2762.5,1288.06 ccw(c-2741.59,1308.97) -2741.59,1279.4 U125B.4@-2731.1,1279.4 ; v1(-2790,1500.29) -2790,1519.53 cw(c-2781.46,1519.53) C464A.1@-2787.5,1525.56 C496A.2@-2762.5,1525.56 ccw(c-2741.89,1546.17) -2741.89,1517.03 U117A.4@-2731.1,1517.03 ; v1(-2790,1712.64) -2790,1732.03 cw(c-2781.46,1732.03) C465A.1@-2787.5,1738.06 C488A.2@-2762.5,1738.06 ccw(c-2741.59,1758.97) -2741.59,1729.4 U125A.4@-2731.1,1729.4 ; v1(-2402.89,-1649.7) -2402.89,-1631.42 cw(c-2393.01,-1631.42) C400H.1@-2400,-1624.44 C424H.2@-2375,-1624.44 ccw(c-2354.39,-1603.83) -2354.39,-1632.97 U101H.4@-2343.6,-1632.97 ; v1(-2402.89,-1199.7) -2402.89,-1181.42 cw(c-2393.01,-1181.42) C400G.1@-2400,-1174.44 C424G.2@-2375,-1174.44 ccw(c-2354.39,-1153.83) -2354.39,-1182.97 U101G.4@-2343.6,-1182.97 ; v1(-2402.89,-749.7) -2402.89,-731.42 cw(c-2393.01,-731.42) C400F.1@-2400,-724.44 C424F.2@-2375,-724.44 ccw(c-2354.39,-703.83) -2354.39,-732.97 U101F.4@-2343.6,-732.97 ; v1(-2402.89,-299.7) -2402.89,-281.42 cw(c-2393.01,-281.42) C400E.1@-2400,-274.44 C424E.2@-2375,-274.44 ccw(c-2354.39,-253.83) -2354.39,-282.97 U101E.4@-2343.6,-282.97 ; v1(-2402.89,150.3) -2402.89,168.58 cw(c-2393.01,168.58) C400D.1@-2400,175.56 C424D.2@-2375,175.56 ccw(c-2354.39,196.17) -2354.39,167.03 U101D.4@-2343.6,167.03 ; v1(-2402.89,600.3) -2402.89,618.58 cw(c-2393.01,618.58) C400C.1@-2400,625.56 C424C.2@-2375,625.56 ccw(c-2354.39,646.17) -2354.39,617.03 U101C.4@-2343.6,617.03 ; v1(-2402.89,1050.3) -2402.89,1068.58 cw(c-2393.01,1068.58) C400B.1@-2400,1075.56 C424B.2@-2375,1075.56 ccw(c-2354.39,1096.17) -2354.39,1067.03 U101B.4@-2343.6,1067.03 ; v1(-2402.89,1500.3) -2402.89,1518.58 cw(c-2393.01,1518.58) C400A.1@-2400,1525.56 C424A.2@-2375,1525.56 ccw(c-2354.39,1546.17) -2354.39,1517.03 U101A.4@-2343.6,1517.03 ; v1(-2402.5,-1436.71) -2402.5,-1417.97 cw(c-2393.96,-1417.97) C401H.1@-2400,-1411.94 C416H.2@-2375,-1411.94 ccw(c-2354.39,-1391.33) -2354.39,-1420.47 U102H.4@-2343.6,-1420.47 ; v1(-2402.5,-986.71) -2402.5,-967.97 cw(c-2393.96,-967.97) C401G.1@-2400,-961.94 C416G.2@-2375,-961.94 ccw(c-2354.39,-941.33) -2354.39,-970.47 U102G.4@-2343.6,-970.47 ; v1(-2402.5,-536.71) -2402.5,-517.97 cw(c-2393.96,-517.97) C401F.1@-2400,-511.94 C416F.2@-2375,-511.94 ccw(c-2354.39,-491.33) -2354.39,-520.47 U102F.4@-2343.6,-520.47 ; v1(-2402.5,-86.71) -2402.5,-67.97 cw(c-2393.96,-67.97) C401E.1@-2400,-61.94 C416E.2@-2375,-61.94 ccw(c-2354.39,-41.33) -2354.39,-70.47 U102E.4@-2343.6,-70.47 ; v1(-2402.5,363.29) -2402.5,382.03 cw(c-2393.96,382.03) C401D.1@-2400,388.06 C416D.2@-2375,388.06 ccw(c-2354.39,408.67) -2354.39,379.53 U102D.4@-2343.6,379.53 ; v1(-2402.5,813.29) -2402.5,832.03 cw(c-2393.96,832.03) C401C.1@-2400,838.06 C416C.2@-2375,838.06 ccw(c-2354.39,858.67) -2354.39,829.53 U102C.4@-2343.6,829.53 ; v1(-2402.5,1263.29) -2402.5,1282.03 cw(c-2393.96,1282.03) C401B.1@-2400,1288.06 C416B.2@-2375,1288.06 ccw(c-2354.39,1308.67) -2354.39,1279.53 U102B.4@-2343.6,1279.53 ; v1(-2402.5,1713.29) -2402.5,1732.03 cw(c-2393.96,1732.03) C401A.1@-2400,1738.06 C416A.2@-2375,1738.06 ccw(c-2354.39,1758.67) -2354.39,1729.53 U102A.4@-2343.6,1729.53
  Bottom Layer w30: FR7.1@1012.5,-1230.12 1012.5,-1450 ccw(c1112.5,-1450) 1112.5,-1550 TP16.1@1350,-1550 R326.1@1764.57,-1550 ; D10.1@1720,-1641.25 1727.35,-1641.25 1751.54,-1617.07 1751.54,-1565 1759.88,-1556.65 1759.88,-1554.69 R326.1@1764.57,-1550 ; C128.1@1737.5,-1467.62 cw(c1737.5,-1496.65) 1766.54,-1496.65 R326.1@1766.54,-1550 R326.1@1764.57,-1550
  other v1: -2297.5,-1687.5 -2278.75,-1687.5 -2692.5,-1675 -2675,-1675 -2657.5,-1675 -2305,-1675 -2287.5,-1675 -2270,-1675 -2683.75,-1662.5 -2666.25,-1662.5 -2296.25,-1662.5 -2278.75,-1662.5 -2692.5,-1650 -2675,-1650 -2657.5,-1650 -2305,-1650 -2287.5,-1650 -2270,-1650 -2296.25,-1475 -2278.75,-1475 -2692.5,-1462.5 -2675,-1462.5 -2657.5,-1462.5 -2305,-1462.5 -2287.5,-1462.5 -2270,-1462.5 -2683.75,-1450 -2666.25,-1450 -2296.25,-1450 -2278.75,-1450 -2692.5,-1437.5 -2675,-1437.5 -2657.5,-1437.5 -2305,-1437.5 -2287.5,-1437.5 -2270,-1437.5 -2297.5,-1237.5 -2278.75,-1237.5 -2692.5,-1225 -2675,-1225 -2657.5,-1225 -2305,-1225 -2287.5,-1225 -2270,-1225 -2683.75,-1212.5 -2666.25,-1212.5 -2296.25,-1212.5 -2278.75,-1212.5 -2692.5,-1200 -2675,-1200 -2657.5,-1200 -2305,-1200 -2287.5,-1200 -2270,-1200 -2296.25,-1025 -2278.75,-1025 -2692.5,-1012.5 -2675,-1012.5 -2657.5,-1012.5 -2305,-1012.5 -2287.5,-1012.5 -2270,-1012.5 -2683.75,-1000 -2666.25,-1000 -2296.25,-1000 -2278.75,-1000 -2692.5,-987.5 -2675,-987.5 -2657.5,-987.5 -2305,-987.5 -2287.5,-987.5 -2270,-987.5 -2297.5,-787.5 -2278.75,-787.5 -2692.5,-775 -2675,-775 -2657.5,-775 -2305,-775 -2287.5,-775 -2270,-775 -2683.75,-762.5 -2666.25,-762.5 -2296.25,-762.5 -2278.75,-762.5 -2692.5,-750 -2675,-750 -2657.5,-750 -2305,-750 -2287.5,-750 -2270,-750 -2296.25,-575 -2278.75,-575 -2692.5,-562.5 -2675,-562.5 -2657.5,-562.5 -2305,-562.5 -2287.5,-562.5 -2270,-562.5 -2683.75,-550 -2666.25,-550 -2296.25,-550 -2278.75,-550 -2692.5,-537.5 -2675,-537.5 -2657.5,-537.5 -2305,-537.5 -2287.5,-537.5 -2270,-537.5 -2297.5,-337.5 -2278.75,-337.5 -2692.5,-325 -2675,-325 -2657.5,-325 -2305,-325 -2287.5,-325 -2270,-325 -2683.75,-312.5 -2666.25,-312.5 -2296.25,-312.5 -2278.75,-312.5 -2692.5,-300 -2675,-300 -2657.5,-300 -2305,-300 -2287.5,-300 -2270,-300 -2296.25,-125 -2278.75,-125 -2692.5,-112.5 -2675,-112.5 -2657.5,-112.5 -2305,-112.5 -2287.5,-112.5 -2270,-112.5 -2683.75,-100 -2666.25,-100 -2296.25,-100 -2278.75,-100 -2692.5,-87.5 -2675,-87.5 -2657.5,-87.5 -2305,-87.5 -2287.5,-87.5 -2270,-87.5 -2297.5,112.5 -2278.75,112.5 -2692.5,125 -2675,125 -2657.5,125 -2305,125 -2287.5,125 -2270,125 -2683.75,137.5 -2666.25,137.5 -2296.25,137.5 -2278.75,137.5 -2692.5,150 -2675,150 -2657.5,150 -2305,150 -2287.5,150 -2270,150 -2296.25,325 -2278.75,325 -2692.5,337.5 -2675,337.5 -2657.5,337.5 -2305,337.5 -2287.5,337.5 -2270,337.5 -2683.75,350 -2666.25,350 -2296.25,350 -2278.75,350 -2692.5,362.5 -2675,362.5 -2657.5,362.5 -2305,362.5 -2287.5,362.5 -2270,362.5 -2297.5,562.5 -2278.75,562.5 -2692.5,575 -2675,575 -2657.5,575 -2305,575 -2287.5,575 -2270,575 -2683.75,587.5 -2666.25,587.5 -2296.25,587.5 -2278.75,587.5 -2692.5,600 -2675,600 -2657.5,600 -2305,600 -2287.5,600 -2270,600 -2296.25,775 -2278.75,775 -2692.5,787.5 -2675,787.5 -2657.5,787.5 -2305,787.5 -2287.5,787.5 -2270,787.5 -2683.75,800 -2666.25,800 -2296.25,800 -2278.75,800 -2692.5,812.5 -2675,812.5 -2657.5,812.5 -2305,812.5 -2287.5,812.5 -2270,812.5 -2297.5,1012.5 -2278.75,1012.5 -2692.5,1025 -2675,1025 -2657.5,1025 -2305,1025 -2287.5,1025 -2270,1025 -2683.75,1037.5 -2666.25,1037.5 -2296.25,1037.5 -2278.75,1037.5 -2692.5,1050 -2675,1050 -2657.5,1050 -2305,1050 -2287.5,1050 -2270,1050 -2296.25,1225 -2278.75,1225 -2692.5,1237.5 -2675,1237.5 -2657.5,1237.5 -2305,1237.5 -2287.5,1237.5 -2270,1237.5 -2683.75,1250 -2666.25,1250 -2296.25,1250 -2278.75,1250 -2692.5,1262.5 -2675,1262.5 -2657.5,1262.5 -2305,1262.5 -2287.5,1262.5 -2270,1262.5 -2297.5,1462.5 -2278.75,1462.5 -2692.5,1475 -2675,1475 -2657.5,1475 -2305,1475 -2287.5,1475 -2270,1475 -2683.75,1487.5 -2666.25,1487.5 -2296.25,1487.5 -2278.75,1487.5 -2692.5,1500 -2675,1500 -2657.5,1500 -2305,1500 -2287.5,1500 -2270,1500 -2296.25,1675 -2278.75,1675 -2692.5,1687.5 -2675,1687.5 -2657.5,1687.5 -2305,1687.5 -2287.5,1687.5 -2270,1687.5 -2683.75,1700 -2666.25,1700 -2296.25,1700 -2278.75,1700 -2692.5,1712.5 -2675,1712.5 -2657.5,1712.5 -2305,1712.5 -2287.5,1712.5 -2270,1712.5
ACLK1: U34A.45 U100.3 | length 2087.2
  Top Layer w5: U34A.45@-1913.58,1495.38 -1913.58,1463.58 -1880,1430 v1(-1637.5,1430)
  Bottom Layer w5: v1(-1637.5,1430) -1585.47,1430 cw(c-1585.47,1232.03) -1387.5,1232.03 -1387.5,-74.7 ccw(c-1350,-74.7) -1350,-112.2 -1313.78,-112.2 U100.3@-1313.78,-111.61
ACLK2: U34B.45 U100.13 | length 2069.7
  Top Layer w5: U34B.45@-1913.58,1045.38 -1913.58,1013.58 -1880,980 v1(-1637.5,980)
  Bottom Layer w5: v1(-1637.5,980) -1524.21,980 cw(c-1524.21,968.29) -1512.5,968.29 -1512.5,900.36 ccw(c-1500,900.36) -1487.5,900.36 -1487.5,968.12 cw(c-1475,968.12) -1462.5,968.12 -1462.5,900.01 ccw(c-1450,900.01) -1437.5,900.01 -1437.5,968.7 cw(c-1425,968.7) -1412.5,968.7 -1412.5,-37.2 cw(c-1512.5,-37.2) -1512.5,-137.2 U100.13@-1536.22,-137.2
ACLK3: U34C.45 U100.15 | length 2069.3
  Top Layer w5: U34C.45@-1913.58,595.38 -1913.58,563.58 -1880,530 v1(-1637.5,530)
  Bottom Layer w5: v1(-1637.5,530) -1525,530 ccw(c-1525,542.5) -1512.5,542.5 -1512.5,745.15 cw(c-1500,745.15) -1487.5,745.15 -1487.5,542.35 ccw(c-1475,542.35) -1462.5,542.35 -1462.5,746.03 cw(c-1450,746.03) -1437.5,746.03 -1437.5,12.5 cw(c-1536.02,12.5) -1536.02,-86.02 U100.15@-1536.22,-86.02
ACLK4: U34D.45 U100.16 | length 2067.9
  Top Layer w5: U34D.45@-1913.58,145.38 -1913.58,113.58 -1880,80 v1(-1637.5,80)
  Bottom Layer w5: v1(-1637.5,80) -1550,80 ccw(c-1550,92.5) -1537.5,92.5 -1537.5,422.6 cw(c-1525,422.6) -1512.5,422.6 -1512.5,92.38 ccw(c-1500,92.38) -1487.5,92.38 -1487.5,422.5 cw(c-1475,422.5) -1462.5,422.5 -1462.5,0 cw(c-1522.93,0) -1522.93,-60.43 U100.16@-1536.22,-60.43
ACLK5: U34E.45 U100.9 | length 2069.4
  Top Layer w5: U34E.45@-1913.58,-304.62 -1913.58,-336.42 -1880,-370 v1(-1637.5,-370)
  Bottom Layer w5: v1(-1637.5,-370) -1565,-370 cw(c-1565,-397.5) -1537.5,-397.5 -1537.5,-717.08 ccw(c-1525,-717.08) -1512.5,-717.08 -1512.5,-382.46 cw(c-1500,-382.46) -1487.5,-382.46 -1487.5,-717.04 ccw(c-1475,-717.1) -1462.5,-717.05 -1462.5,-300 ccw(c-1522.93,-300) -1522.93,-239.57 U100.9@-1536.22,-239.57
ACLK6: U34F.45 U100.11 | length 2067.3
  Top Layer w5: U34F.45@-1913.58,-754.62 -1913.58,-786.42 -1880,-820 v1(-1637.5,-820)
  Bottom Layer w5: v1(-1637.5,-820) -1537.5,-820 cw(c-1537.5,-845) -1512.5,-845 -1512.5,-1032.5 ccw(c-1500,-1032.5) -1487.5,-1032.5 -1487.5,-832.77 cw(c-1475,-832.77) -1462.5,-832.77 -1462.5,-1033 ccw(c-1450,-1033) -1437.5,-1033 -1437.5,-287.11 ccw(c-1536.22,-287.11) U100.11@-1536.22,-188.39
ACLK7: U34G.45 U100.6 | length 2069.4
  Top Layer w5: U34G.45@-1913.58,-1204.62 -1913.58,-1236.42 -1880,-1270 v1(-1637.5,-1270)
  Bottom Layer w5: v1(-1637.5,-1270) -1512.5,-1270 cw(c-1512.5,-1295) -1487.5,-1295 ; -1487.5,-1295.42 -1487.5,-1365.16 ccw(c-1475.01,-1364.58) -1462.5,-1364.57 -1462.5,-1282.48 cw(c-1450,-1282.48) -1437.5,-1282.48 -1437.5,-1364.41 ccw(c-1425,-1364.41) -1412.5,-1364.41 -1412.5,-287.11 cw(c-1313.78,-287.11) U100.6@-1313.78,-188.39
